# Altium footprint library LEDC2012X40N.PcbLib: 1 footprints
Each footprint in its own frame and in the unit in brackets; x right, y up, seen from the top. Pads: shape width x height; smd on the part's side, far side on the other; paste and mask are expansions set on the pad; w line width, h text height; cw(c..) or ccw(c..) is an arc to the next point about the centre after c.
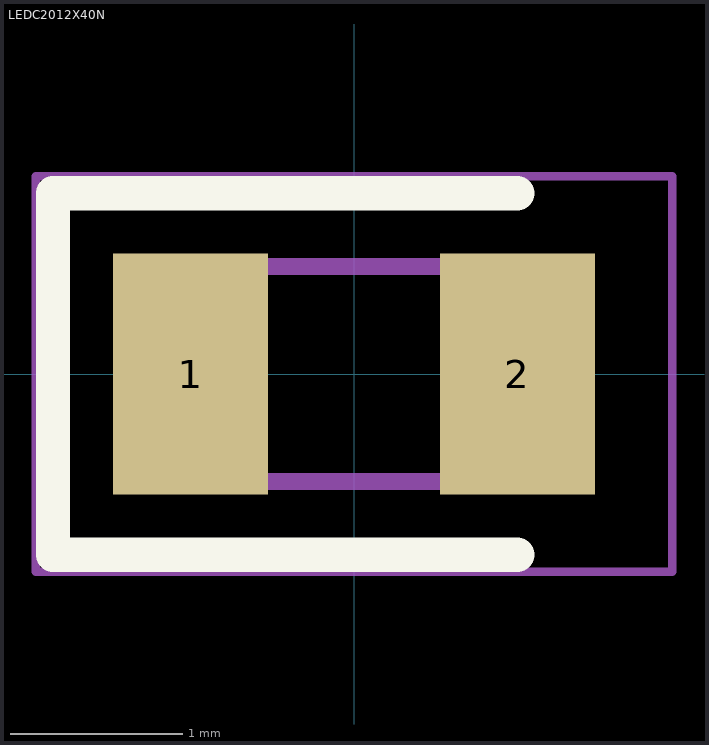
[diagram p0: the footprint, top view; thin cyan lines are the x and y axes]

## LEDC2012X40N [mm]
pads (2):
  rect 0.9x1.4 smd: 1(-0.95,0) 2(0.95,0)
Top Overlay:
  lines w0.2: 0.95,-1.05 -1.75,-1.05 -1.75,1.05 0.95,1.05
Mechanical 15:
  lines w0.1: -1,0.208 -0.583,0.625 ; -1,-0.625 1,-0.625 1,0.625 -1,0.625 -1,-0.625
Mechanical 20:
  lines w0.05: -1.85,-1.15 1.85,-1.15 1.85,1.15 -1.85,1.15 -1.85,-1.15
